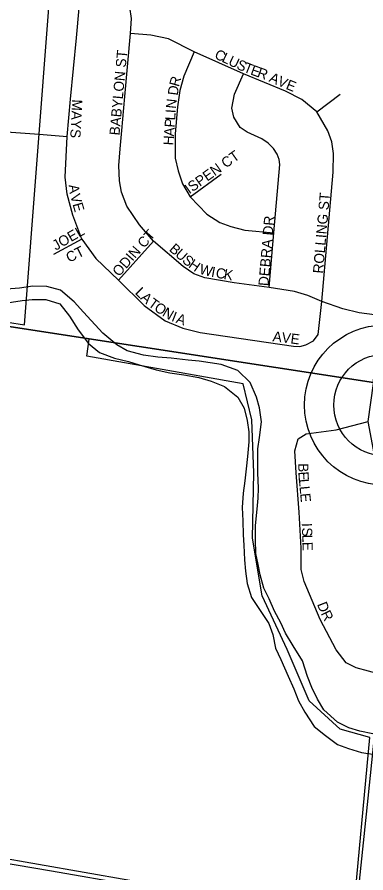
# Model space of a CAD drawing. Extents: x -209 to 4852, y 0 to 905.
# Drawn here: x 518.26 to 524.74, y 261.1 to 277 of the extents above; entities that cross this region are included whole.
import ezdxf

# ---------------------------------------------------------------- set-up
doc = ezdxf.new("R2010")
doc.units = 0
for name, color, linetype in [('GM_X_Airport_Location_Class_2', 7, 'Continuous'), ('GM_X_County_Road', 7, 'Continuous'), ('GM_X_County_Road_Text', 7, 'Continuous'), ('GM_X_Interstate_Location', 7, 'Continuous'), ('GM_X_Minor_River', 7, 'Continuous'), ('GM_X_Township_Subdivision_Text', 7, 'Continuous'), ('GM_X_Township_Text', 7, 'Continuous'), ('GM_X_US_Location', 7, 'Continuous')]:
    doc.layers.add(name, color=color, linetype=linetype)

msp = doc.modelspace()

# ---------------------------------------------------------------- linework, layer by layer
at = {"layer": 'GM_X_Airport_Location_Class_2'}
msp.add_lwpolyline([(515.765, 275.071), (516.93, 274.958), (518.062, 274.869), (518.665, 274.825)], dxfattribs=at)
at = {"layer": 'GM_X_County_Road'}
for points in [[(524.868, 263.68), (524.626, 263.73), (524.423, 263.795), (524.212, 263.898), (523.959, 264.124), (523.841, 264.324), (523.732, 264.539), (523.652, 264.746), (523.559, 265.037), (523.39, 265.314), (523.243, 265.553), (523.156, 265.745), (523.039, 265.96), (522.944, 266.191), (522.842, 266.39), (522.771, 266.635), (522.737, 266.826), (522.695, 267.033), (522.685, 267.292), (522.69, 267.55), (522.719, 267.854), (522.738, 268.059), (522.742, 268.249), (522.732, 268.531), (522.729, 268.744), (522.733, 268.98), (522.76, 269.185), (522.796, 269.481), (522.763, 269.741), (522.707, 269.94), (522.59, 270.208), (522.36, 270.434), (522.051, 270.546), (521.846, 270.573), (521.642, 270.607), (521.438, 270.627), (521.12, 270.663), (520.87, 270.683), (520.605, 270.719), (520.303, 270.801), (520.108, 270.911), (519.847, 271.129), (519.49, 271.517), (519.319, 271.71), (519.065, 271.928), (518.809, 271.994), (518.551, 271.999), (518.3, 271.966), (518.057, 271.948)], [(518.074, 271.689), (518.348, 271.737), (518.539, 271.756), (518.789, 271.751), (519.053, 271.67), (519.231, 271.446), (519.392, 271.191), (519.585, 270.936), (519.786, 270.765), (520.065, 270.661), (520.329, 270.602), (520.525, 270.538), (520.842, 270.448), (521.092, 270.39), (521.357, 270.354), (521.636, 270.303), (521.863, 270.238), (522.111, 270.134), (522.358, 269.939), (522.475, 269.731), (522.531, 269.502), (522.565, 269.296), (522.561, 269.105), (522.541, 268.832), (522.514, 268.604), (522.487, 268.384), (522.459, 268.156), (522.439, 267.89), (522.449, 267.639), (522.459, 267.38), (522.471, 267.189), (522.481, 266.915), (522.499, 266.702), (522.533, 266.473), (522.611, 266.212), (522.751, 266.012), (522.936, 265.734), (523.007, 265.527), (523.056, 265.275), (523.158, 265.06), (523.296, 264.753), (523.397, 264.515), (523.484, 264.293), (523.601, 264.085), (523.778, 263.815), (523.987, 263.652), (524.212, 263.48), (524.415, 263.407), (524.657, 263.334), (524.906, 263.299)]]:
    msp.add_lwpolyline(points, dxfattribs=at)
at = {"layer": 'GM_X_County_Road_Text'}
for points in [[(524.533, 260.114), (524.78, 262.485), (524.978, 264.412), (525.016, 264.783), (525.111, 265.7), (525.126, 265.845), (525.126, 267.179), (525.027, 268.019), (524.879, 268.957), (524.78, 269.485), (524.879, 270.193), (524.881, 270.213), (524.882, 270.275)], [(517.249, 261.412), (518.895, 261.132), (520.387, 260.873), (521.669, 260.651), (522.843, 260.448), (522.897, 260.437), (524.533, 260.114)]]:
    msp.add_lwpolyline(points, dxfattribs=at)
at = {"layer": 'GM_X_Minor_River'}
for points in [[(517.218, 291.054), (537.772, 289.267), (535.846, 268.527), (515.439, 271.658)], [(515.439, 271.658), (535.846, 268.527), (534.233, 247.886), (513.823, 252.487)]]:
    msp.add_lwpolyline(points, close=True, dxfattribs=at)
at = {"layer": 'GM_X_Township_Subdivision_Text'}
for radius in [1.488, 0.943]:
    msp.add_circle((525.085, 269.791), radius, dxfattribs=at)
at = {"layer": 'GM_X_Township_Text'}
for points in [[(519.458, 272.875), (519.293, 273.32), (519.19, 273.712), (519.151, 274.024), (519.19, 274.783), (519.249, 275.474), (519.36, 276.617), (519.461, 277.728)], [(520.792, 272.84), (520.53, 273.138), (520.294, 273.485), (520.196, 273.749), (520.16, 273.959), (520.149, 274.242), (520.17, 274.553), (520.203, 274.896), (520.258, 275.525), (520.367, 276.696), (520.38, 276.976), (520.349, 277.186), (520.25, 277.398)], [(523.829, 275.242), (523.55, 275.471), (523.246, 275.622), (522.465, 275.946), (521.545, 276.357), (521.071, 276.595), (520.742, 276.668), (520.367, 276.696)], [(521.545, 276.357), (521.354, 275.903), (521.278, 275.637), (521.238, 275.335), (521.194, 274.833), (521.194, 274.381), (521.247, 274.143), (521.329, 273.904), (521.473, 273.659), (521.784, 273.342), (522.025, 273.185), (522.226, 273.107), (522.49, 273.041), (523.028, 272.994)], [(522.943, 271.973), (523.028, 272.994), (523.138, 274.261), (523.124, 274.354), (523.089, 274.452), (523.019, 274.56), (522.924, 274.661), (522.807, 274.739), (522.67, 274.799), (522.531, 274.866), (522.4, 274.948), (522.283, 275.144), (522.25, 275.309), (522.297, 275.569), (522.465, 275.946)], [(523.829, 275.242), (524.26, 275.572)], [(523.762, 270.985), (523.854, 271.104), (523.921, 271.714), (524.131, 274.122), (524.138, 274.464), (524.103, 274.681), (524.034, 274.888), (523.829, 275.242)], [(518.665, 274.825), (519.19, 274.783)], [(521.473, 273.659), (522.046, 274.084)], [(519.458, 272.875), (518.935, 272.59)], [(519.458, 272.875), (519.722, 272.515), (520.139, 272.113), (520.619, 271.64), (521.009, 271.354), (521.339, 271.22), (521.656, 271.137), (523.393, 270.884), (523.514, 270.879), (523.622, 270.908), (523.762, 270.985)], [(520.139, 272.113), (520.792, 272.84)], [(524.924, 271.469), (524.901, 271.47), (524.616, 271.506), (524.31, 271.582), (523.921, 271.714), (523.662, 271.83), (523.411, 271.903), (522.943, 271.973), (522.291, 272.064), (521.747, 272.154), (521.54, 272.232), (521.34, 272.369), (520.792, 272.84)], [(525.016, 264.783), (524.559, 264.908), (524.372, 265.001), (524.186, 265.244), (523.887, 265.804), (523.589, 266.513), (523.533, 266.737), (523.533, 267.129), (523.496, 267.802), (523.44, 268.53), (523.421, 268.94), (523.477, 269.165), (523.626, 269.258), (524.186, 269.333), (524.78, 269.485)]]:
    msp.add_lwpolyline(points, dxfattribs=at)
at = {"layer": 'GM_X_US_Location'}
for points in [[(505.239, 276.856), (505.907, 276.835), (507.322, 276.623), (508.465, 275.747), (510.473, 277.806), (510.486, 277.327), (512.095, 278.778), (512.354, 278.483), (516.025, 282.023), (516.207, 282.027), (516.009, 279.412), (515.718, 275.598), (515.379, 271.686), (515.077, 268.055), (514.788, 264.427), (515.869, 264.333), (515.814, 263.71), (517.984, 263.52), (517.801, 261.404), (522.051, 260.662)], [(524.494, 260.216), (524.814, 263.61), (524.263, 263.766), (523.682, 264.295), (523.277, 265.246), (522.812, 266.245), (522.629, 267.314), (522.654, 268.53), (522.621, 269.519), (522.46, 270.186), (519.551, 270.698), (519.598, 271.015), (518.065, 271.25), (518.076, 271.33), (518.392, 271.281), (518.859, 277.34)]]:
    msp.add_lwpolyline(points, dxfattribs=at)

# ---------------------------------------------------------------- texts
at = {"layer": 'GM_X_Interstate_Location'}
for s, height, rotation, p in [('BABYLON ST', 0.1894, 84.7421, (520.159, 274.797)), ('C', 0.189, 334.8467, (521.91, 276.243)), ('L', 0.189, 334.828, (522.046, 276.179)), ('U', 0.189, 334.8509, (522.166, 276.122)), ('S', 0.189, 335.2482, (522.319, 276.051)), ('T', 0.189, 338.3953, (522.45, 275.991)), ('E', 0.189, 340.1087, (522.58, 275.939)), ('R', 0.189, 340.186, (522.705, 275.894)), ('R', 0.189, 74.3849, (521.261, 275.696)), ('A', 0.189, 336.0064, (522.926, 275.81)), ('V', 0.189, 336.0218, (523.079, 275.742)), ('E', 0.189, 338.3058, (523.238, 275.671)), ('D', 0.189, 83.0105, (521.243, 275.538)), ('MAYS', 0.1894, 267.1392, (519.28, 275.475)), ('N', 0.189, 83.9567, (521.208, 275.293)), ('L', 0.189, 85.9261, (521.193, 275.078)), ('I', 0.189, 85.93, (521.203, 275.212)), ('P', 0.189, 85.8988, (521.184, 274.945)), ('A', 0.189, 85.9097, (521.172, 274.779)), ('H', 0.189, 85.9097, (521.16, 274.613)), ('ISPEN CT', 0.1894, 35.3113, (521.457, 273.706)), ('A', 0.189, 277.6726, (519.214, 273.879)), ('V', 0.189, 284.9878, (519.241, 273.688)), ('ROLLING ST', 0.1894, 85.0606, (523.942, 272.23)), ('E', 0.189, 285.9436, (519.285, 273.524)), ('DEBRA DR', 0.1894, 85.1005, (522.928, 271.997)), ('JOEL', 0.1894, 29.7432, (518.977, 272.658)), ('ODIN CT', 0.1894, 48.6194, (520.151, 272.167)), ('B', 0.189, 318.6085, (521.069, 272.67)), ('CT', 0.1894, 26.565, (519.224, 272.434)), ('U', 0.189, 318.6208, (521.181, 272.571)), ('S', 0.189, 320.2738, (521.311, 272.457)), ('H', 0.189, 325.3568, (521.428, 272.361)), ('W', 0.189, 345.2243, (521.63, 272.236)), ('I', 0.189, 349.215, (521.853, 272.178)), ('C', 0.189, 349.9731, (521.938, 272.162)), ('K', 0.189, 349.9901, (522.086, 272.136)), ('L', 0.189, 315.2318, (520.437, 271.869)), ('A', 0.189, 317.5816, (520.537, 271.769)), ('T', 0.189, 323.9946, (520.678, 271.642)), ('O', 0.189, 324.9665, (520.789, 271.562)), ('N', 0.189, 329.5626, (520.94, 271.457)), ('I', 0.189, 338.297, (521.112, 271.359)), ('A', 0.189, 340.6458, (521.197, 271.325)), ('A', 0.189, 352.791, (522.999, 270.979)), ('V', 0.189, 352.7902, (523.165, 270.958)), ('E', 0.189, 352.7665, (523.33, 270.937)), ('B', 0.189, 270.6558, (523.48, 268.71)), ('E', 0.189, 273.7378, (523.482, 268.549)), ('L', 0.189, 275.272, (523.492, 268.411)), ('L', 0.189, 275.3734, (523.504, 268.277)), ('E', 0.189, 275.3734, (523.516, 268.145)), ('I', 0.189, 272.0111, (523.547, 267.595)), ('S', 0.189, 272.0272, (523.55, 267.512)), ('L', 0.189, 272.022, (523.555, 267.379)), ('E', 0.189, 271.7216, (523.559, 267.246)), ('D', 0.189, 291.3184, (523.828, 266.089)), ('R', 0.189, 296.2262, (523.896, 265.918))]:
    msp.add_text(s, height=height, rotation=rotation, dxfattribs=at).set_placement(p)

doc.saveas('drawing.dxf')
